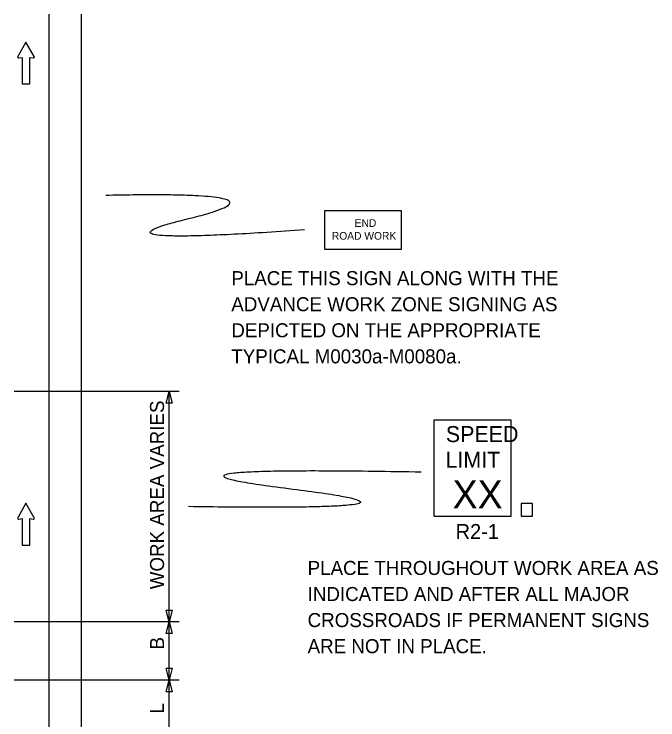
# Model space of a CAD drawing. Extents: x 16745 to 18475, y 7012 to 8195.
# Drawn here: x 17058 to 17379.3, y 7839.4 to 8191.4 of the extents above; entities that cross this region are included whole.
import ezdxf

# ---------------------------------------------------------------- set-up
doc = ezdxf.new("R2010")
doc.units = 0
for name, color, linetype in [('MT_SCRATCH_LEVEL_E', 7, 'Continuous'), ('PAVT_EDGE_EX', 7, 'Continuous'), ('TRAFFIC_SIGNS_PR', 7, 'Continuous'), ('TYPICAL_TEXT_DIMEN_PR', 7, 'Continuous')]:
    doc.layers.add(name, color=color, linetype=linetype)

msp = doc.modelspace()

# ---------------------------------------------------------------- linework, layer by layer
at = {"layer": 'MT_SCRATCH_LEVEL_E'}
for p, q in [((17063.89, 8177.47), (17059.78, 8170.23)), ((17063.89, 8177.47), (17059.78, 8170.23)), ((17068.04, 8170.23), (17063.89, 8177.47)), ((17068.04, 8170.23), (17063.89, 8177.47)), ((17060.26, 8169.55), (17062.04, 8169.86)), ((17060.26, 8169.55), (17062.04, 8169.86)), ((17062.04, 8169.86), (17062.04, 8156.6)), ((17062.04, 8169.86), (17062.04, 8156.6)), ((17065.78, 8156.6), (17065.78, 8169.86)), ((17065.78, 8169.86), (17067.56, 8169.55)), ((17065.78, 8156.6), (17065.78, 8169.86)), ((17065.78, 8169.86), (17067.56, 8169.55)), ((17062.04, 8156.6), (17065.78, 8156.6)), ((17062.04, 8156.6), (17065.78, 8156.6)), ((17063.89, 7947.47), (17059.78, 7940.23)), ((17063.89, 7947.47), (17059.78, 7940.23)), ((17068.04, 7940.23), (17063.89, 7947.47)), ((17068.04, 7940.23), (17063.89, 7947.47)), ((17060.26, 7939.54), (17062.04, 7939.86)), ((17060.26, 7939.54), (17062.04, 7939.86)), ((17062.04, 7939.86), (17062.04, 7926.6)), ((17062.04, 7939.86), (17062.04, 7926.6)), ((17065.78, 7926.6), (17065.78, 7939.86)), ((17065.78, 7939.86), (17067.56, 7939.54)), ((17065.78, 7926.6), (17065.78, 7939.86)), ((17065.78, 7939.86), (17067.56, 7939.54)), ((17062.04, 7926.6), (17065.78, 7926.6)), ((17062.04, 7926.6), (17065.78, 7926.6))]:
    msp.add_line(p, q, dxfattribs=at)
for centre, start, end in [((17060.19, 8170), 150.4248, 279.9638), ((17060.19, 8170), 150.4248, 279.9638), ((17067.63, 8170), 260.0362, 29.7731), ((17067.63, 8170), 260.0362, 29.7731), ((17060.19, 7940), 150.4248, 279.9638), ((17060.19, 7940), 150.4248, 279.9638), ((17067.63, 7940), 260.0362, 29.7731), ((17067.63, 7940), 260.0362, 29.7731)]:
    msp.add_arc(centre, 0.463, start, end, dxfattribs=at)
at = {"layer": 'PAVT_EDGE_EX'}
for p, q in [((17075.37, 8191.42), (17075.37, 7362.23)), ((17091.37, 8191.42), (17091.37, 7362.23))]:
    msp.add_line(p, q, dxfattribs=at)
at = {"layer": 'TRAFFIC_SIGNS_PR'}
for p, q in [((17267.71, 7989.1), (17306.11, 7989.1)), ((17267.71, 7941.1), (17267.71, 7989.1)), ((17306.11, 7941.1), (17306.11, 7989.1)), ((17267.71, 7941.1), (17306.11, 7941.1))]:
    msp.add_line(p, q, dxfattribs=at)
for points in [[(17212.95, 8074.18), (17251.35, 8074.18), (17251.35, 8093.38), (17212.95, 8093.38)], [(17311.12, 7941.1), (17316.72, 7941.1), (17316.72, 7947.27), (17311.12, 7947.27)]]:
    msp.add_lwpolyline(points, close=True, dxfattribs=at)
for points in [[(17203, 8083.8), (17087.78, 8075.56), (17201.69, 8103.14), (17103.74, 8100.98)], [(17261.15, 7962.95), (17105.52, 7965.85), (17285.89, 7943.61), (17144.99, 7945.78)]]:
    msp.add_open_spline(points, degree=2, dxfattribs=at)
at = {"layer": 'TYPICAL_TEXT_DIMEN_PR'}
for p, q in [((17140.37, 8003.23), (17057.97, 8003.23)), ((17133.8, 7997.37), (17135.37, 8003.23)), ((17135.37, 7888.32), (17135.37, 8003.23)), ((17135.37, 8003.23), (17136.94, 7997.37)), ((17135.37, 7997.37), (17133.8, 7997.37)), ((17136.94, 7997.37), (17135.37, 7997.37)), ((17135.37, 7888.32), (17133.8, 7894.18)), ((17133.8, 7894.18), (17135.37, 7894.18)), ((17135.37, 7894.18), (17136.94, 7894.18)), ((17136.94, 7894.18), (17135.37, 7888.32)), ((17140.37, 7888.32), (17057.97, 7888.32)), ((17133.8, 7882.46), (17135.37, 7888.32)), ((17135.37, 7859.27), (17135.37, 7888.32)), ((17135.37, 7888.32), (17136.94, 7882.46)), ((17135.37, 7882.46), (17133.8, 7882.46)), ((17136.94, 7882.46), (17135.37, 7882.46)), ((17135.37, 7859.27), (17133.8, 7865.13)), ((17133.8, 7865.13), (17135.37, 7865.13)), ((17135.37, 7865.13), (17136.94, 7865.13)), ((17136.94, 7865.13), (17135.37, 7859.27)), ((17140.37, 7859.27), (17057.97, 7859.27)), ((17133.8, 7853.4), (17135.37, 7859.27)), ((17135.37, 7828.7), (17135.37, 7859.27)), ((17135.37, 7859.27), (17136.94, 7853.4)), ((17135.37, 7853.4), (17133.8, 7853.4)), ((17136.94, 7853.4), (17135.37, 7853.4))]:
    msp.add_line(p, q, dxfattribs=at)

# ---------------------------------------------------------------- texts
at = {"layer": 'TRAFFIC_SIGNS_PR'}
for s, height, p in [('END', 3.831, (17227.95, 8085.31)), ('ROAD WORK', 3.831, (17216.56, 8078.92)), ('PLACE THIS SIGN ALONG WITH THE', 7, (17166.39, 8056.23)), ('ADVANCE WORK ZONE SIGNING AS', 7, (17166.39, 8043.23)), ('DEPICTED ON THE APPROPRIATE', 7, (17166.39, 8030.23)), ('TYPICAL M0030a-M0080a.', 7, (17166.39, 8017.23)), ('SPEED', 8, (17273.47, 7977.96)), ('LIMIT', 8, (17273.31, 7965.16)), ('XX', 14.031, (17276.82, 7944.86)), ('R2-1', 7.44, (17278.38, 7929.66)), ('PLACE THROUGHOUT WORK AREA AS', 7, (17204.48, 7911.69)), ('INDICATED AND AFTER ALL MAJOR ', 7, (17204.48, 7898.69)), ('CROSSROADS IF PERMANENT SIGNS', 7, (17204.48, 7885.69)), ('ARE NOT IN PLACE.', 7, (17204.48, 7872.69))]:
    msp.add_text(s, height=height, dxfattribs=at).set_placement(p)
at = {"layer": 'TYPICAL_TEXT_DIMEN_PR'}
for s, p in [('WORK AREA VARIES', (17132.81, 7904.55)), ('B', (17132.81, 7874.53)), ('L', (17132.81, 7842.56))]:
    msp.add_text(s, height=7, rotation=90, dxfattribs=at).set_placement(p)

doc.saveas('drawing.dxf')
